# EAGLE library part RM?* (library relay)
Power Relay SCHRACK 3 pole 10 A, DC- or AC-coil Source: http://www.schrack.com/.. 5829.pdf Socket with PCB terminals Source: http://www.schrack.com/.. 5841.pdf
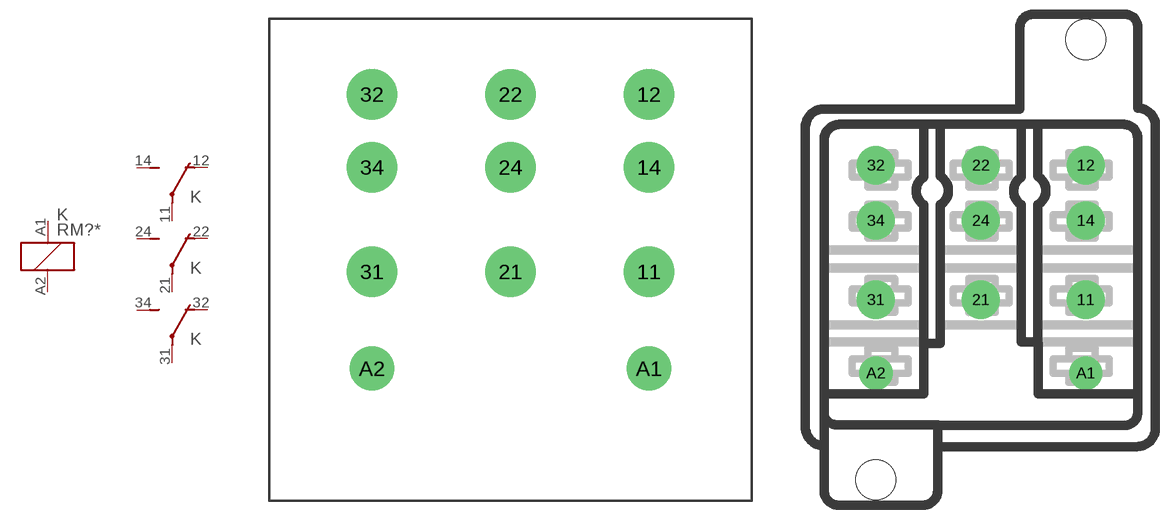
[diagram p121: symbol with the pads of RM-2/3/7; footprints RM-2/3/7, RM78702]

Designator prefix K; gates 1=K 2=U 3=U 4=U

## RM3506 (OC_FARNELL: unknown; OC_NEWARK: unknown), RM3512 (OC_FARNELL: unknown; OC_NEWARK: unknown), RM3524 (OC_FARNELL: unknown; OC_NEWARK: unknown), RM3548 (OC_FARNELL: unknown; OC_NEWARK: unknown), RM3615 (OC_FARNELL: unknown; OC_NEWARK: unknown), RM3730 (OC_FARNELL: unknown; OC_NEWARK: unknown), RM3900 (OC_FARNELL: unknown; OC_NEWARK: unknown), RM3R06 (OC_FARNELL: unknown; OC_NEWARK: unknown), RM3R12 (OC_FARNELL: unknown; OC_NEWARK: unknown), RM3R24 (OC_FARNELL: unknown; OC_NEWARK: unknown), RM3R48 (OC_FARNELL: unknown; OC_NEWARK: unknown), RM3S15 (OC_FARNELL: unknown; OC_NEWARK: unknown), RM3T30 (OC_FARNELL: unknown; OC_NEWARK: unknown), RM3V00 (OC_FARNELL: unknown; OC_NEWARK: unknown)  [RM-2/3/7]
11  2:P  pas
12  2:O  pas
14  2:S  pas
21  3:P  pas
22  3:O  pas
24  3:S  pas
31  4:P  pas
32  4:O  pas
34  4:S  pas
A1  1:1  pas
A2  1:2  pas

## RM7506 (OC_FARNELL: unknown; OC_NEWARK: unknown), RM7512 (OC_FARNELL: unknown; OC_NEWARK: unknown), RM7524 (OC_FARNELL: unknown; OC_NEWARK: unknown), RM7548 (OC_FARNELL: unknown; OC_NEWARK: unknown), RM7615 (OC_FARNELL: unknown; OC_NEWARK: unknown), RM7730 (OC_FARNELL: unknown; OC_NEWARK: unknown), RM7900 (OC_FARNELL: unknown; OC_NEWARK: unknown), RM7R06 (OC_FARNELL: unknown; OC_NEWARK: unknown), RM7R12 (OC_FARNELL: unknown; OC_NEWARK: unknown), RM7R24 (OC_FARNELL: unknown; OC_NEWARK: unknown), RM7R48 (OC_FARNELL: unknown; OC_NEWARK: unknown), RM7S15 (OC_FARNELL: unknown; OC_NEWARK: unknown), RM7T30 (OC_FARNELL: unknown; OC_NEWARK: unknown), RM7V00 (OC_FARNELL: unknown; OC_NEWARK: unknown)  [RM-2/3/7]
Pads as for RM-2/3/7

## RM78702 (MF: TYCO ELECTRONICS; MPN: RM78702; OC_FARNELL: 1652632; OC_NEWARK: 36K3468)  [RM78702]
Pads as for RM-2/3/7

## Footprint RM-2/3/7 (pad centres in mm)
Power Relay SCHRACK 2 / 3 pole 10 / 16 A, DC- or AC-coil Source: http://www.schrack.com/.. 5829.pdf
drill 2 pad 4 round: 11 11,-0.95; 12 11,13.15; 14 11,7.35; 21 0,-0.95; 22 0,13.15; 24 0,7.35; 31 -11,-0.95; 32 -11,13.15; 34 -11,7.35
drill 2 pad 3.5 round: A1 11,-8.65; A2 -11,-8.65

## Footprint RM78702 (pad centres in mm)
Power Relay Socket with PCB terminals SCHRACK 3 pole 10 A, DC- or AC-coil Source: http://www.schrack.com/.. 5841.pdf
drill 2 pad 4 round: 11 11,-0.95; 12 11,13.15; 14 11,7.35; 21 0,-0.95; 22 0,13.15; 24 0,7.35; 31 -11,-0.95; 32 -11,13.15; 34 -11,7.35
drill 2 pad 3.5 round: A1 11,-8.65; A2 -11,-8.65
hole 4.2 at -11,-19.85
hole 4.2 at 11,26.35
